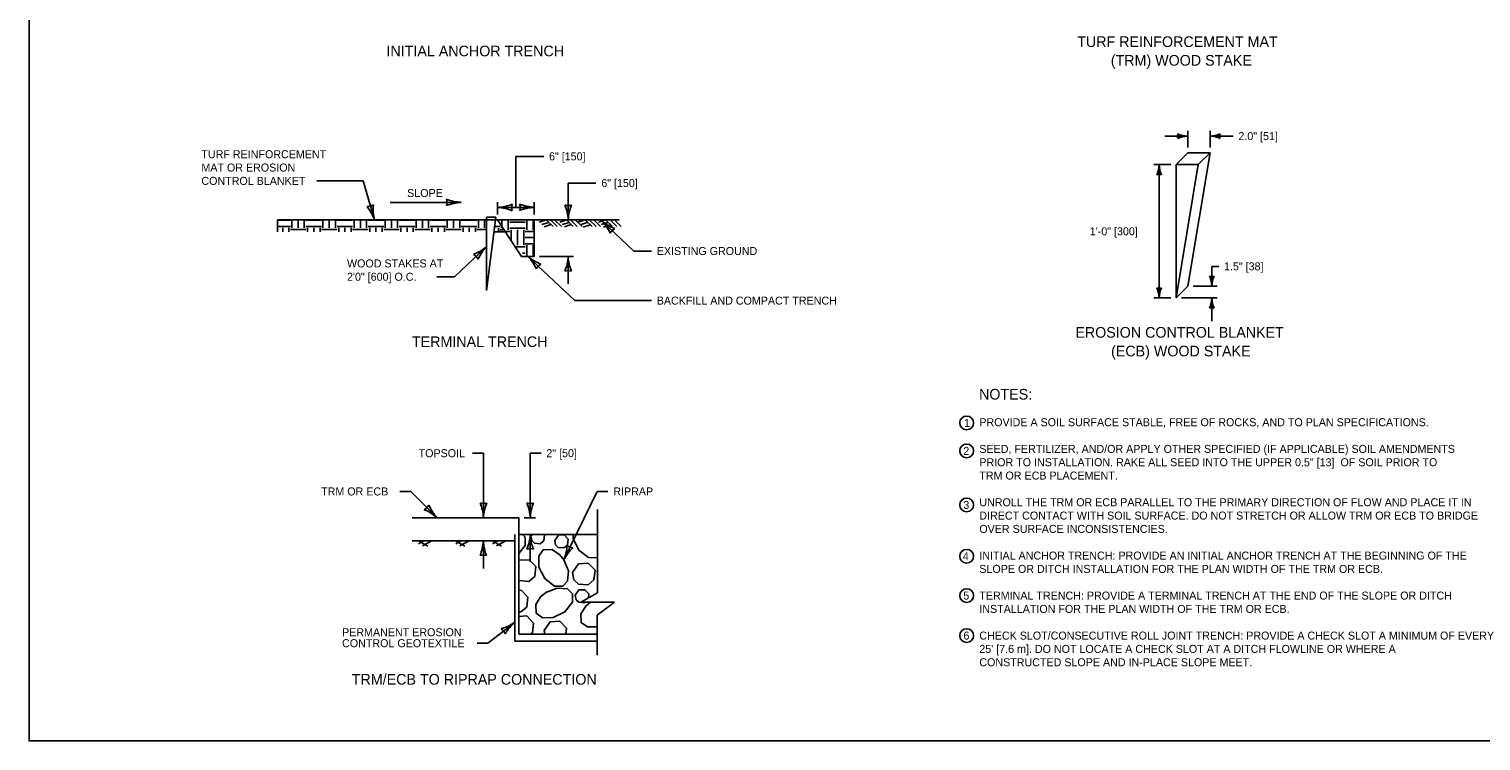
# Model space of a CAD drawing. Extents: x 49977.1 to 50021, y 49987.6 to 50011.4.
# Drawn here: x 49999.38 to 50010.27, y 49987.8 to 49993.14 of the extents above; entities that cross this region are included whole.
import ezdxf

# ---------------------------------------------------------------- set-up
doc = ezdxf.new("R2010")
doc.units = 0
for name, color, linetype in [('Level 1', 7, 'Continuous'), ('Level 2', 7, 'Continuous'), ('Level 3', 7, 'Continuous')]:
    doc.layers.add(name, color=color, linetype=linetype)

msp = doc.modelspace()

# ---------------------------------------------------------------- linework, layer by layer
at = {"layer": 'Level 1'}
for p, q in [((50007.985, 49992.121), (50008.073, 49992.209)), ((50008.24, 49992.209), (50008.073, 49991.209)), ((50008.073, 49992.209), (50008.24, 49992.209)), ((50008.151, 49992.121), (50008.24, 49992.209)), ((50007.985, 49992.121), (50007.985, 49991.121)), ((50008.151, 49992.121), (50007.985, 49991.121)), ((50007.985, 49992.121), (50008.151, 49992.121)), ((50002.883, 49991.728), (50002.814, 49991.178)), ((50002.814, 49991.728), (50002.814, 49991.178)), ((50002.814, 49991.728), (50002.883, 49991.728)), ((50002.897, 49991.708), (50001.247, 49991.708)), ((50001.247, 49991.616), (50001.247, 49991.708)), ((50002.814, 49991.708), (50001.247, 49991.708)), ((50001.247, 49991.704), (50001.344, 49991.704)), ((50001.247, 49991.657), (50001.344, 49991.657)), ((50001.286, 49991.646), (50001.286, 49991.616)), ((50001.333, 49991.646), (50001.333, 49991.616)), ((50001.344, 49991.635), (50001.46, 49991.635)), ((50001.355, 49991.708), (50001.355, 49991.646)), ((50001.402, 49991.708), (50001.402, 49991.646)), ((50001.448, 49991.708), (50001.448, 49991.646)), ((50001.46, 49991.704), (50001.577, 49991.704)), ((50001.46, 49991.657), (50001.577, 49991.657)), ((50001.473, 49991.646), (50001.473, 49991.616)), ((50001.519, 49991.646), (50001.519, 49991.616)), ((50001.566, 49991.646), (50001.566, 49991.616)), ((50001.577, 49991.635), (50001.693, 49991.635)), ((50001.588, 49991.708), (50001.588, 49991.646)), ((50001.635, 49991.708), (50001.635, 49991.646)), ((50001.681, 49991.708), (50001.681, 49991.646)), ((50001.693, 49991.704), (50001.81, 49991.704)), ((50001.693, 49991.657), (50001.81, 49991.657)), ((50001.706, 49991.646), (50001.706, 49991.616)), ((50001.752, 49991.646), (50001.752, 49991.616)), ((50001.799, 49991.646), (50001.799, 49991.616)), ((50001.81, 49991.635), (50001.926, 49991.635)), ((50001.821, 49991.708), (50001.821, 49991.646)), ((50001.868, 49991.708), (50001.868, 49991.646)), ((50001.914, 49991.708), (50001.914, 49991.646)), ((50001.926, 49991.704), (50002.043, 49991.704)), ((50001.926, 49991.657), (50002.043, 49991.657)), ((50001.939, 49991.646), (50001.939, 49991.616)), ((50001.985, 49991.646), (50001.985, 49991.616)), ((50002.032, 49991.646), (50002.032, 49991.616)), ((50002.043, 49991.635), (50002.159, 49991.635)), ((50002.054, 49991.708), (50002.054, 49991.646)), ((50002.101, 49991.708), (50002.101, 49991.646)), ((50002.147, 49991.708), (50002.147, 49991.646)), ((50002.159, 49991.704), (50002.276, 49991.704)), ((50002.159, 49991.657), (50002.276, 49991.657)), ((50002.172, 49991.646), (50002.172, 49991.616)), ((50002.218, 49991.646), (50002.218, 49991.616)), ((50002.265, 49991.646), (50002.265, 49991.616)), ((50002.276, 49991.635), (50002.392, 49991.635)), ((50002.287, 49991.708), (50002.287, 49991.646)), ((50002.334, 49991.708), (50002.334, 49991.646)), ((50002.38, 49991.708), (50002.38, 49991.646)), ((50002.392, 49991.704), (50002.509, 49991.704)), ((50002.392, 49991.657), (50002.509, 49991.657)), ((50002.405, 49991.646), (50002.405, 49991.616)), ((50002.451, 49991.646), (50002.451, 49991.616)), ((50002.498, 49991.646), (50002.498, 49991.616)), ((50002.509, 49991.635), (50002.625, 49991.635)), ((50002.52, 49991.708), (50002.52, 49991.646)), ((50002.567, 49991.708), (50002.567, 49991.646)), ((50002.613, 49991.708), (50002.613, 49991.646)), ((50002.625, 49991.704), (50002.741, 49991.704)), ((50002.625, 49991.657), (50002.741, 49991.657)), ((50002.638, 49991.646), (50002.638, 49991.616)), ((50002.684, 49991.646), (50002.684, 49991.616)), ((50002.731, 49991.646), (50002.731, 49991.616)), ((50002.741, 49991.635), (50002.814, 49991.635)), ((50002.753, 49991.708), (50002.753, 49991.646)), ((50002.8, 49991.708), (50002.8, 49991.646)), ((50002.814, 49991.616), (50002.814, 49991.708)), ((50002.957, 49991.616), (50002.869, 49991.616)), ((50002.874, 49991.657), (50002.914, 49991.657)), ((50002.897, 49991.708), (50003.076, 49991.433)), ((50002.897, 49991.708), (50003.172, 49991.708)), ((50002.903, 49991.645), (50002.903, 49991.616)), ((50002.914, 49991.633), (50002.946, 49991.633)), ((50002.927, 49991.663), (50002.927, 49991.644)), ((50002.93, 49991.708), (50002.93, 49991.657)), ((50002.954, 49991.62), (50002.988, 49991.62)), ((50002.977, 49991.708), (50002.977, 49991.631)), ((50002.988, 49991.69), (50003.104, 49991.69)), ((50002.988, 49991.644), (50003.104, 49991.644)), ((50002.999, 49991.632), (50002.999, 49991.551)), ((50003.046, 49991.632), (50003.046, 49991.516)), ((50003.093, 49991.632), (50003.093, 49991.516)), ((50003.104, 49991.62), (50003.172, 49991.62)), ((50003.117, 49991.708), (50003.117, 49991.631)), ((50003.163, 49991.708), (50003.163, 49991.631)), ((50003.172, 49991.708), (50003.172, 49991.433)), ((50003.81, 49991.708), (50003.172, 49991.708)), ((50003.262, 49991.708), (50003.21, 49991.69)), ((50003.282, 49991.688), (50003.23, 49991.671)), ((50003.297, 49991.672), (50003.246, 49991.655)), ((50003.313, 49991.656), (50003.262, 49991.708)), ((50003.345, 49991.656), (50003.293, 49991.708)), ((50003.377, 49991.656), (50003.325, 49991.708)), ((50003.416, 49991.708), (50003.365, 49991.69)), ((50003.434, 49991.688), (50003.382, 49991.671)), ((50003.45, 49991.671), (50003.398, 49991.654)), ((50003.465, 49991.656), (50003.413, 49991.708)), ((50003.495, 49991.656), (50003.444, 49991.708)), ((50003.532, 49991.656), (50003.48, 49991.708)), ((50003.553, 49991.708), (50003.501, 49991.69)), ((50003.576, 49991.689), (50003.524, 49991.672)), ((50003.591, 49991.669), (50003.54, 49991.652)), ((50003.606, 49991.656), (50003.555, 49991.708)), ((50003.636, 49991.656), (50003.584, 49991.708)), ((50003.67, 49991.656), (50003.618, 49991.708)), ((50003.704, 49991.708), (50003.653, 49991.69)), ((50003.726, 49991.688), (50003.674, 49991.671)), ((50003.744, 49991.67), (50003.692, 49991.653)), ((50003.758, 49991.656), (50003.706, 49991.708)), ((50003.792, 49991.656), (50003.741, 49991.708)), ((50003.825, 49991.656), (50003.774, 49991.708)), ((50002.984, 49991.574), (50002.988, 49991.574)), ((50003.029, 49991.505), (50003.104, 49991.505)), ((50003.104, 49991.574), (50003.172, 49991.574)), ((50003.104, 49991.527), (50003.172, 49991.527)), ((50003.117, 49991.516), (50003.117, 49991.433)), ((50003.163, 49991.516), (50003.163, 49991.433)), ((50003.085, 49991.458), (50003.104, 49991.458)), ((50008.073, 49991.209), (50007.985, 49991.121)), ((50003.057, 49989.473), (50002.257, 49989.473)), ((50003.057, 49988.69), (50003.057, 49989.473)), ((50003.646, 49989.534), (50003.646, 49988.91)), ((50003.027, 49988.547), (50003.027, 49989.348)), ((50003.057, 49989.348), (50003.646, 49989.348)), ((50003.147, 49989.334), (50003.156, 49989.348)), ((50003.027, 49989.299), (50002.257, 49989.299)), ((50002.304, 49989.299), (50002.373, 49989.259)), ((50002.344, 49989.299), (50002.305, 49989.278)), ((50002.405, 49989.299), (50002.335, 49989.261)), ((50002.582, 49989.299), (50002.651, 49989.259)), ((50002.622, 49989.299), (50002.583, 49989.278)), ((50002.684, 49989.299), (50002.613, 49989.261)), ((50002.858, 49989.299), (50002.927, 49989.259)), ((50002.898, 49989.299), (50002.859, 49989.278)), ((50002.96, 49989.299), (50002.889, 49989.261)), ((50003.646, 49988.91), (50003.522, 49988.839)), ((50003.522, 49988.839), (50003.774, 49988.839)), ((50003.774, 49988.839), (50003.645, 49988.743)), ((50003.057, 49988.599), (50003.057, 49988.69)), ((50003.645, 49988.743), (50003.645, 49988.547)), ((50003.057, 49988.599), (50003.645, 49988.599)), ((50003.251, 49988.599), (50003.246, 49988.627)), ((50003.645, 49988.547), (50003.027, 49988.547)), ((50003.645, 49988.547), (50003.645, 49988.441))]:
    msp.add_line(p, q, dxfattribs=at)
msp.add_lwpolyline([(49999.384, 49998.999), (50016.75, 49998.999), (50016.75, 49987.799), (49999.384, 49987.799)], close=True, dxfattribs=at)
for points in [[(50003.172, 49991.708), (50003.172, 49991.433), (50003.076, 49991.433), (50002.897, 49991.708)], [(50003.083, 49989.348), (50003.104, 49989.327), (50003.103, 49989.264), (50003.057, 49989.205)], [(50003.244, 49989.348), (50003.248, 49989.344), (50003.243, 49989.3), (50003.217, 49989.278), (50003.174, 49989.281), (50003.153, 49989.301), (50003.147, 49989.334)], [(50003.326, 49989.303), (50003.353, 49989.341), (50003.396, 49989.344), (50003.427, 49989.312), (50003.422, 49989.268), (50003.395, 49989.246), (50003.352, 49989.249), (50003.332, 49989.269), (50003.326, 49989.302)], [(50003.646, 49989.176), (50003.643, 49989.173), (50003.579, 49989.174), (50003.507, 49989.23), (50003.464, 49989.317), (50003.463, 49989.348)], [(50003.394, 49989.158), (50003.428, 49989.074), (50003.421, 49988.996), (50003.386, 49988.959), (50003.323, 49988.96), (50003.251, 49989.016), (50003.207, 49989.103), (50003.206, 49989.185), (50003.239, 49989.231), (50003.304, 49989.235), (50003.362, 49989.198), (50003.396, 49989.155)], [(50003.057, 49989.149), (50003.061, 49989.154), (50003.133, 49989.158), (50003.184, 49989.106), (50003.176, 49989.033), (50003.132, 49988.995), (50003.06, 49989.001), (50003.057, 49989.003)], [(50003.46, 49989.063), (50003.505, 49989.128), (50003.577, 49989.132), (50003.628, 49989.08), (50003.62, 49989.007), (50003.576, 49988.969), (50003.504, 49988.975), (50003.47, 49989.007), (50003.46, 49989.063)], [(50003.646, 49989.051), (50003.644, 49989.072), (50003.646, 49989.075)], [(50003.057, 49988.928), (50003.073, 49988.929), (50003.123, 49988.877), (50003.116, 49988.803), (50003.071, 49988.766), (50003.057, 49988.767)], [(50003.26, 49988.912), (50003.344, 49988.945), (50003.422, 49988.939), (50003.46, 49988.903), (50003.458, 49988.84), (50003.402, 49988.768), (50003.315, 49988.725), (50003.233, 49988.723), (50003.187, 49988.756), (50003.183, 49988.821), (50003.22, 49988.88), (50003.263, 49988.914)], [(50003.48, 49988.892), (50003.507, 49988.931), (50003.551, 49988.933), (50003.581, 49988.902), (50003.578, 49988.871)], [(50003.554, 49988.839), (50003.55, 49988.835), (50003.507, 49988.839), (50003.487, 49988.858), (50003.48, 49988.892)], [(50003.645, 49988.655), (50003.571, 49988.654), (50003.525, 49988.686), (50003.521, 49988.752), (50003.558, 49988.81), (50003.594, 49988.839)], [(50003.057, 49988.732), (50003.116, 49988.736), (50003.166, 49988.683), (50003.159, 49988.61), (50003.145, 49988.599)], [(50003.246, 49988.627), (50003.291, 49988.692), (50003.364, 49988.696), (50003.414, 49988.644), (50003.41, 49988.599)]]:
    msp.add_lwpolyline(points, dxfattribs=at)
at = {"layer": 'Level 2'}
for centre in [(50006.415, 49990.184), (50006.415, 49989.974), (50006.415, 49989.569), (50006.415, 49989.184), (50006.415, 49988.889), (50006.415, 49988.589)]:
    msp.add_circle(centre, 0.0517, dxfattribs=at)
at = {"layer": 'Level 3'}
for p, q in [((50008.073, 49992.249), (50008.073, 49992.375)), ((50008.24, 49992.249), (50008.24, 49992.375)), ((50007.9, 49992.335), (50008.073, 49992.335)), ((50008.24, 49992.335), (50008.413, 49992.335)), ((50003.034, 49992.183), (50003.035, 49991.8)), ((50003.243, 49992.183), (50003.034, 49992.183)), ((50007.945, 49992.121), (50007.819, 49992.121)), ((50007.859, 49991.121), (50007.859, 49992.121)), ((50001.542, 49991.999), (50001.888, 49991.999)), ((50001.973, 49991.708), (50001.888, 49991.999)), ((50003.635, 49991.983), (50003.426, 49991.983)), ((50003.427, 49991.983), (50003.427, 49991.708)), ((50002.092, 49991.838), (50002.624, 49991.838)), ((50002.897, 49991.84), (50002.897, 49991.748)), ((50003.172, 49991.84), (50003.172, 49991.748)), ((50003.172, 49991.8), (50002.897, 49991.8)), ((50003.678, 49991.699), (50003.918, 49991.473)), ((50002.814, 49991.506), (50002.575, 49991.28)), ((50003.124, 49991.433), (50003.476, 49991.101)), ((50003.467, 49991.433), (50003.212, 49991.433)), ((50003.427, 49991.433), (50003.427, 49991.226)), ((50004.051, 49991.473), (50003.918, 49991.473)), ((50002.441, 49991.28), (50002.575, 49991.28)), ((50008.254, 49991.209), (50008.254, 49991.358)), ((50008.254, 49991.358), (50008.305, 49991.358)), ((50008.113, 49991.209), (50008.294, 49991.209)), ((50004.051, 49991.101), (50003.476, 49991.101)), ((50007.945, 49991.121), (50007.819, 49991.121)), ((50008.025, 49991.121), (50008.294, 49991.121)), ((50008.254, 49990.947), (50008.254, 49991.121)), ((50002.791, 49989.957), (50002.709, 49989.957)), ((50002.791, 49989.957), (50002.791, 49989.473)), ((50003.142, 49989.957), (50003.142, 49989.473)), ((50003.223, 49989.957), (50003.142, 49989.957)), ((50002.246, 49989.67), (50002.164, 49989.67)), ((50002.443, 49989.473), (50002.246, 49989.67)), ((50003.393, 49989.157), (50003.644, 49989.67)), ((50003.725, 49989.67), (50003.644, 49989.67)), ((50003.182, 49989.473), (50003.097, 49989.473)), ((50003.142, 49989.348), (50003.142, 49989.141)), ((50002.791, 49989.299), (50002.791, 49989.093)), ((50003.027, 49988.688), (50002.825, 49988.532)), ((50002.825, 49988.532), (50002.743, 49988.532))]:
    msp.add_line(p, q, dxfattribs=at)
for centre, radius, start, end in [((50008.082, 49992.557), 0.222, 247.456, 267.6395), ((50007.945, 49992.335), 0.0548, 342.1388, 17.8612), ((50008.085, 49992.102), 0.233, 92.8273, 112.0772), ((50008.228, 49992.568), 0.233, 272.8273, 292.0772), ((50008.231, 49992.113), 0.222, 67.456, 87.6395), ((50008.368, 49992.335), 0.0548, 162.1388, 197.8612), ((50007.637, 49992.13), 0.222, 337.456, 357.6395), ((50007.859, 49991.992), 0.0548, 72.1388, 107.8612), ((50008.092, 49992.132), 0.233, 182.8273, 202.0772), ((50002.637, 49992.16), 0.322, 247.456, 267.6395), ((50002.438, 49991.838), 0.0794, 342.1388, 17.8612), ((50002.641, 49991.5), 0.338, 92.8273, 112.0772), ((50002.881, 49992.138), 0.338, 272.8273, 292.0772), ((50003.083, 49991.8), 0.0794, 162.1388, 197.8612), ((50003.186, 49992.123), 0.322, 247.456, 267.6395), ((50002.987, 49991.8), 0.0794, 342.1388, 17.8612), ((50001.921, 49991.886), 0.0794, 268.5507, 304.273), ((50001.654, 49991.596), 0.338, 19.2392, 38.489), ((50002.286, 49991.786), 0.322, 173.8679, 194.0514), ((50002.884, 49991.478), 0.322, 67.456, 87.6395), ((50003.189, 49991.463), 0.338, 92.8273, 112.0772), ((50003.427, 49991.894), 0.0794, 252.1388, 287.8612), ((50003.089, 49991.691), 0.338, 2.8273, 22.0772), ((50003.749, 49991.694), 0.322, 157.456, 177.6395), ((50003.448, 49991.474), 0.322, 24.16, 44.3435), ((50003.898, 49991.956), 0.338, 229.5313, 248.7812), ((50003.814, 49991.572), 0.0794, 118.8428, 154.5652), ((50002.595, 49991.763), 0.338, 291.2188, 310.4687), ((50003.045, 49991.281), 0.322, 135.6565, 155.84), ((50002.679, 49991.378), 0.0794, 25.4348, 61.1572), ((50002.894, 49991.207), 0.322, 24.16, 44.3435), ((50003.344, 49991.69), 0.338, 229.5313, 248.7812), ((50003.105, 49991.446), 0.322, 337.456, 357.6395), ((50003.764, 49991.449), 0.338, 182.8273, 202.0772), ((50003.26, 49991.305), 0.0794, 118.8428, 154.5652), ((50003.427, 49991.247), 0.0794, 72.1388, 107.8612), ((50008.254, 49991.337), 0.0548, 252.1388, 287.8612), ((50008.021, 49991.198), 0.233, 2.8273, 22.0772), ((50008.476, 49991.2), 0.222, 157.456, 177.6395), ((50007.859, 49991.249), 0.0548, 252.1388, 287.8612), ((50007.626, 49991.109), 0.233, 2.8273, 22.0772), ((50008.081, 49991.112), 0.222, 157.456, 177.6395), ((50008.032, 49991.13), 0.222, 337.456, 357.6395), ((50008.487, 49991.132), 0.233, 182.8273, 202.0772), ((50008.254, 49990.992), 0.0548, 72.1388, 107.8612), ((50002.311, 49989.604), 0.0794, 297.1388, 332.8612), ((50002.68, 49989.691), 0.322, 202.456, 222.6395), ((50002.791, 49989.659), 0.0794, 252.1388, 287.8612), ((50002.453, 49989.456), 0.338, 2.8273, 22.0772), ((50003.113, 49989.46), 0.322, 157.456, 177.6395), ((50003.142, 49989.659), 0.0794, 252.1388, 287.8612), ((50002.804, 49989.456), 0.338, 2.8273, 22.0772), ((50003.464, 49989.46), 0.322, 157.456, 177.6395), ((50002.216, 49989.222), 0.338, 47.8273, 67.0772), ((50002.82, 49989.361), 0.322, 337.456, 357.6395), ((50003.479, 49989.364), 0.338, 182.8273, 202.0772), ((50002.468, 49989.313), 0.322, 337.456, 357.6395), ((50003.128, 49989.316), 0.338, 182.8273, 202.0772), ((50003.142, 49989.162), 0.0794, 72.1388, 107.8612), ((50003.081, 49989.286), 0.338, 337.5749, 356.8247), ((50003.679, 49989.008), 0.322, 132.2036, 152.3871), ((50003.472, 49989.325), 0.0794, 226.8864, 262.6088), ((50002.791, 49989.113), 0.0794, 72.1388, 107.8612), ((50002.841, 49988.952), 0.322, 285.1023, 305.2858), ((50003.246, 49988.431), 0.338, 130.4736, 149.7234), ((50002.88, 49988.575), 0.0794, 19.7851, 55.5074)]:
    msp.add_arc(centre, radius, start, end, dxfattribs=at)

# ---------------------------------------------------------------- texts
at = {"layer": 'Level 2'}
for s, height, p in [('TURF REINFORCEMENT MAT ', 0.08, (50007.244, 49993.003)), ('INITIAL ANCHOR TRENCH', 0.08, (50002.064, 49992.933)), ('(TRM) WOOD STAKE', 0.08, (50007.496, 49992.863)), ('2.0" [51]', 0.06, (50008.453, 49992.305)), ('TURF REINFORCEMENT ', 0.06, (50000.676, 49992.169)), ('6" [150]', 0.06, (50003.283, 49992.153)), ('MAT OR EROSION', 0.06, (50000.676, 49992.069)), ('CONTROL BLANKET', 0.06, (50000.676, 49991.969)), ('SLOPE', 0.06, (50002.219, 49991.878)), ('6" [150]', 0.06, (50003.675, 49991.953)), ('1\'-0" [300]', 0.06, (50007.338, 49991.591)), ('EXISTING GROUND', 0.06, (50004.091, 49991.443)), ('WOOD STAKES AT', 0.06, (50001.768, 49991.35)), ('1.5" [38]', 0.06, (50008.345, 49991.328)), ('2\'0" [600] O.C.', 0.06, (50001.768, 49991.25)), ('BACKFILL AND COMPACT TRENCH', 0.06, (50004.091, 49991.071)), ('EROSION CONTROL BLANKET', 0.08, (50007.23, 49990.823)), ('TERMINAL TRENCH', 0.08, (50002.255, 49990.753)), ('(ECB) WOOD STAKE', 0.08, (50007.498, 49990.683)), ('NOTES:', 0.08, (50006.508, 49990.359)), ('1', 0.06, (50006.396, 49990.154)), ('PROVIDE A SOIL SURFACE STABLE, FREE OF ROCKS, AND TO PLAN SPECIFICATIONS.', 0.06, (50006.51, 49990.159)), ('TOPSOIL', 0.06, (50002.305, 49989.927)), ('2" [50]', 0.06, (50003.263, 49989.927)), ('2', 0.06, (50006.39, 49989.944)), ('SEED, FERTILIZER, AND/OR APPLY OTHER SPECIFIED (IF APPLICABLE) SOIL AMENDMENTS ', 0.06, (50006.51, 49989.959)), ('PRIOR TO INSTALLATION. RAKE ALL SEED INTO THE UPPER 0.5" [13]  OF SOIL PRIOR TO', 0.06, (50006.51, 49989.859)), ('TRM OR ECB PLACEMENT.', 0.06, (50006.51, 49989.759)), ('TRM OR ECB', 0.06, (50001.574, 49989.64)), ('RIPRAP', 0.06, (50003.765, 49989.64)), ('3', 0.06, (50006.39, 49989.539)), ('UNROLL THE TRM OR ECB PARALLEL TO THE PRIMARY DIRECTION OF FLOW AND PLACE IT IN', 0.06, (50006.51, 49989.559)), ('DIRECT CONTACT WITH SOIL SURFACE. DO NOT STRETCH OR ALLOW TRM OR ECB TO BRIDGE ', 0.06, (50006.51, 49989.459)), ('OVER SURFACE INCONSISTENCIES.', 0.06, (50006.51, 49989.359)), ('4', 0.06, (50006.386, 49989.154)), ('INITIAL ANCHOR TRENCH: PROVIDE AN INITIAL ANCHOR TRENCH AT THE BEGINNING OF THE ', 0.06, (50006.51, 49989.159)), ('SLOPE OR DITCH INSTALLATION FOR THE PLAN WIDTH OF THE TRM OR ECB.', 0.06, (50006.51, 49989.059)), ('5', 0.06, (50006.39, 49988.859)), ('TERMINAL TRENCH: PROVIDE A TERMINAL TRENCH AT THE END OF THE SLOPE OR DITCH ', 0.06, (50006.51, 49988.859)), ('INSTALLATION FOR THE PLAN WIDTH OF THE TRM OR ECB.', 0.06, (50006.51, 49988.759)), ('CONTROL GEOTEXTILE', 0.06, (50001.731, 49988.502)), ('PERMANENT EROSION ', 0.06, (50001.731, 49988.584)), ('6', 0.06, (50006.391, 49988.559)), ('CHECK SLOT/CONSECUTIVE ROLL JOINT TRENCH: PROVIDE A CHECK SLOT A MINIMUM OF EVERY', 0.06, (50006.51, 49988.559)), ("25' [7.6 m]. DO NOT LOCATE A CHECK SLOT AT A DITCH FLOWLINE OR WHERE A ", 0.06, (50006.51, 49988.459)), ('CONSTRUCTED SLOPE AND IN-PLACE SLOPE MEET.', 0.06, (50006.51, 49988.359)), ('TRM/ECB TO RIPRAP CONNECTION', 0.08, (50001.804, 49988.221))]:
    msp.add_text(s, height=height, dxfattribs=at).set_placement(p)

doc.saveas('drawing.dxf')
